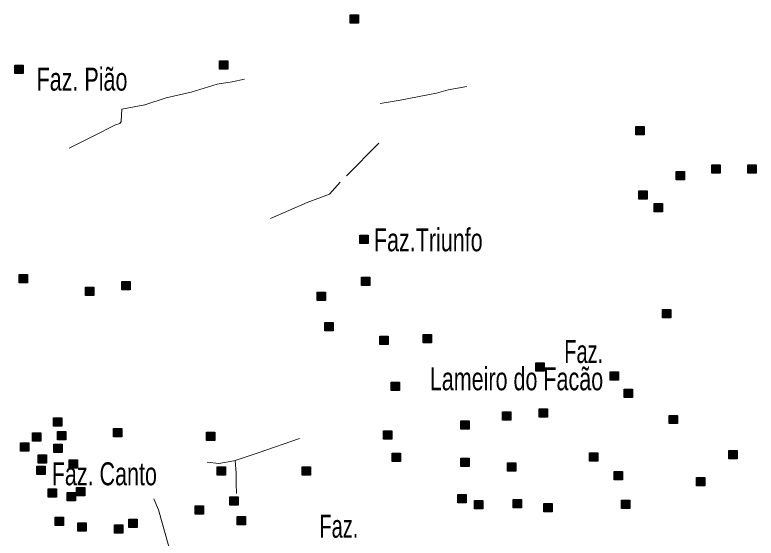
# Model space of a CAD drawing. Extents: x 445.4 to 500, y 8728.7 to 8784.
# Drawn here: x 494.63 to 499.79, y 8734.48 to 8738.12 of the extents above; entities that cross this region are included whole.
import ezdxf
from ezdxf.enums import TextEntityAlignment as Align

# ---------------------------------------------------------------- set-up
doc = ezdxf.new("R2010")
doc.units = 0
doc.header["$LTSCALE"] = 0.064
doc.linetypes.add('DOT_DASHED', pattern=[7.7, 5, -1.2, 0.3, -1.2])
doc.layers.add('2', color=7, linetype='Continuous', lineweight=25)
doc.layers.add('22', color=7, linetype='DOT_DASHED', lineweight=13)
doc.layers.add('61', color=7, linetype='Continuous')

msp = doc.modelspace()

# ---------------------------------------------------------------- hatches: boundary and pattern name
at = {"layer": '2'}
for points in [[(496.9631, 8738.124), (497.0211, 8738.124), (497.0211, 8738.066), (496.9631, 8738.066)], [(494.6266, 8737.7738), (494.6846, 8737.7738), (494.6846, 8737.7158), (494.6266, 8737.7158)], [(496.0512, 8737.8034), (496.1092, 8737.8034), (496.1092, 8737.7454), (496.0512, 8737.7454)], [(498.9517, 8737.3449), (499.0097, 8737.3449), (499.0097, 8737.2869), (498.9517, 8737.2869)], [(499.4806, 8737.0784), (499.5386, 8737.0784), (499.5386, 8737.0204), (499.4806, 8737.0204)], [(499.7323, 8737.0784), (499.7903, 8737.0784), (499.7903, 8737.0204), (499.7323, 8737.0204)], [(499.2326, 8737.031), (499.2906, 8737.031), (499.2906, 8736.973), (499.2326, 8736.973)], [(498.9735, 8736.897), (499.0315, 8736.897), (499.0315, 8736.839), (498.9735, 8736.839)], [(499.0794, 8736.8084), (499.1374, 8736.8084), (499.1374, 8736.7504), (499.0794, 8736.7504)], [(497.0302, 8736.5875), (497.0882, 8736.5875), (497.0882, 8736.5295), (497.0302, 8736.5295)], [(494.6562, 8736.314), (494.7142, 8736.314), (494.7142, 8736.256), (494.6562, 8736.256)], [(495.371, 8736.2647), (495.429, 8736.2647), (495.429, 8736.2067), (495.371, 8736.2067)], [(497.042, 8736.2943), (497.1, 8736.2943), (497.1, 8736.2363), (497.042, 8736.2363)], [(495.1196, 8736.2253), (495.1776, 8736.2253), (495.1776, 8736.1673), (495.1196, 8736.1673)], [(496.7314, 8736.1907), (496.7894, 8736.1907), (496.7894, 8736.1327), (496.7314, 8736.1327)], [(499.1377, 8736.0696), (499.1957, 8736.0696), (499.1957, 8736.0116), (499.1377, 8736.0116)], [(496.7857, 8735.9787), (496.8437, 8735.9787), (496.8437, 8735.9207), (496.7857, 8735.9207)], [(497.1701, 8735.885), (497.2281, 8735.885), (497.2281, 8735.827), (497.1701, 8735.827)], [(497.4708, 8735.8948), (497.5288, 8735.8948), (497.5288, 8735.8368), (497.4708, 8735.8368)], [(498.2546, 8735.6976), (498.3126, 8735.6976), (498.3126, 8735.6396), (498.2546, 8735.6396)], [(498.7729, 8735.6352), (498.8309, 8735.6352), (498.8309, 8735.5772), (498.7729, 8735.5772)], [(497.249, 8735.5644), (497.307, 8735.5644), (497.307, 8735.5064), (497.249, 8735.5064)], [(498.8714, 8735.5148), (498.9294, 8735.5148), (498.9294, 8735.4568), (498.8714, 8735.4568)], [(498.0229, 8735.3576), (498.0809, 8735.3576), (498.0809, 8735.2996), (498.0229, 8735.2996)], [(498.2792, 8735.377), (498.3372, 8735.377), (498.3372, 8735.319), (498.2792, 8735.319)], [(499.1851, 8735.3323), (499.2431, 8735.3323), (499.2431, 8735.2743), (499.1851, 8735.2743)], [(494.8955, 8735.3151), (494.9535, 8735.3151), (494.9535, 8735.2571), (494.8955, 8735.2571)], [(497.7321, 8735.2932), (497.7901, 8735.2932), (497.7901, 8735.2352), (497.7321, 8735.2352)], [(495.3133, 8735.2401), (495.3713, 8735.2401), (495.3713, 8735.1821), (495.3133, 8735.1821)], [(494.7499, 8735.2093), (494.8079, 8735.2093), (494.8079, 8735.1513), (494.7499, 8735.1513)], [(494.9239, 8735.2187), (494.9819, 8735.2187), (494.9819, 8735.1607), (494.9239, 8735.1607)], [(495.9625, 8735.2143), (496.0205, 8735.2143), (496.0205, 8735.1563), (495.9625, 8735.1563)], [(497.1948, 8735.2241), (497.2528, 8735.2241), (497.2528, 8735.1661), (497.1948, 8735.1661)], [(494.6661, 8735.1403), (494.7241, 8735.1403), (494.7241, 8735.0823), (494.6661, 8735.0823)], [(494.8977, 8735.1304), (494.9557, 8735.1304), (494.9557, 8735.0724), (494.8977, 8735.0724)], [(498.6292, 8735.0712), (498.6872, 8735.0712), (498.6872, 8735.0132), (498.6292, 8735.0132)], [(499.601, 8735.0878), (499.659, 8735.0878), (499.659, 8735.0298), (499.601, 8735.0298)], [(494.7893, 8735.0564), (494.8473, 8735.0564), (494.8473, 8734.9984), (494.7893, 8734.9984)], [(495.0062, 8735.0219), (495.0642, 8735.0219), (495.0642, 8734.9639), (495.0062, 8734.9639)], [(497.2554, 8735.068), (497.3134, 8735.068), (497.3134, 8735.01), (497.2554, 8735.01)], [(497.7342, 8735.0337), (497.7922, 8735.0337), (497.7922, 8734.9757), (497.7342, 8734.9757)], [(494.7794, 8734.9775), (494.8374, 8734.9775), (494.8374, 8734.9195), (494.7794, 8734.9195)], [(496.0364, 8734.9726), (496.0944, 8734.9726), (496.0944, 8734.9146), (496.0364, 8734.9146)], [(496.6279, 8734.9726), (496.6859, 8734.9726), (496.6859, 8734.9146), (496.6279, 8734.9146)], [(498.0574, 8735.0022), (498.1154, 8735.0022), (498.1154, 8734.9442), (498.0574, 8734.9442)], [(498.8021, 8734.9418), (498.8601, 8734.9418), (498.8601, 8734.8838), (498.8021, 8734.8838)], [(499.3748, 8734.898), (499.4328, 8734.898), (499.4328, 8734.84), (499.3748, 8734.84)], [(494.8583, 8734.8197), (494.9163, 8734.8197), (494.9163, 8734.7617), (494.8583, 8734.7617)], [(495.056, 8734.8294), (495.114, 8734.8294), (495.114, 8734.7714), (495.056, 8734.7714)], [(494.9914, 8734.7951), (495.0494, 8734.7951), (495.0494, 8734.7371), (494.9914, 8734.7371)], [(496.1251, 8734.7634), (496.1831, 8734.7634), (496.1831, 8734.7054), (496.1251, 8734.7054)], [(497.7131, 8734.7798), (497.7711, 8734.7798), (497.7711, 8734.7218), (497.7131, 8734.7218)], [(497.8291, 8734.7393), (497.8871, 8734.7393), (497.8871, 8734.6813), (497.8291, 8734.6813)], [(498.0968, 8734.7457), (498.1548, 8734.7457), (498.1548, 8734.6877), (498.0968, 8734.6877)], [(498.3116, 8734.7173), (498.3696, 8734.7173), (498.3696, 8734.6593), (498.3116, 8734.6593)], [(498.8532, 8734.741), (498.9112, 8734.741), (498.9112, 8734.683), (498.8532, 8734.683)], [(495.8837, 8734.7009), (495.9417, 8734.7009), (495.9417, 8734.6429), (495.8837, 8734.6429)], [(494.9076, 8734.6225), (494.9656, 8734.6225), (494.9656, 8734.5645), (494.9076, 8734.5645)], [(495.4202, 8734.6077), (495.4782, 8734.6077), (495.4782, 8734.5497), (495.4202, 8734.5497)], [(496.1744, 8734.6274), (496.2324, 8734.6274), (496.2324, 8734.5694), (496.1744, 8734.5694)], [(495.0653, 8734.583), (495.1233, 8734.583), (495.1233, 8734.525), (495.0653, 8734.525)], [(495.3217, 8734.5682), (495.3797, 8734.5682), (495.3797, 8734.5102), (495.3217, 8734.5102)]]:
    msp.add_hatch(color=256, dxfattribs=at).paths.add_polyline_path(points)

# ---------------------------------------------------------------- linework, layer by layer
for points in [[(496.9631, 8738.124), (497.0211, 8738.124), (497.0211, 8738.066), (496.9631, 8738.066)], [(494.6266, 8737.7738), (494.6846, 8737.7738), (494.6846, 8737.7158), (494.6266, 8737.7158)], [(496.0512, 8737.8034), (496.1092, 8737.8034), (496.1092, 8737.7454), (496.0512, 8737.7454)], [(498.9517, 8737.3449), (499.0097, 8737.3449), (499.0097, 8737.2869), (498.9517, 8737.2869)], [(499.4806, 8737.0784), (499.5386, 8737.0784), (499.5386, 8737.0204), (499.4806, 8737.0204)], [(499.7323, 8737.0784), (499.7903, 8737.0784), (499.7903, 8737.0204), (499.7323, 8737.0204)], [(499.2326, 8737.031), (499.2906, 8737.031), (499.2906, 8736.973), (499.2326, 8736.973)], [(498.9735, 8736.897), (499.0315, 8736.897), (499.0315, 8736.839), (498.9735, 8736.839)], [(499.0794, 8736.8084), (499.1374, 8736.8084), (499.1374, 8736.7504), (499.0794, 8736.7504)], [(497.0302, 8736.5875), (497.0882, 8736.5875), (497.0882, 8736.5295), (497.0302, 8736.5295)], [(494.6562, 8736.314), (494.7142, 8736.314), (494.7142, 8736.256), (494.6562, 8736.256)], [(495.371, 8736.2647), (495.429, 8736.2647), (495.429, 8736.2067), (495.371, 8736.2067)], [(497.042, 8736.2943), (497.1, 8736.2943), (497.1, 8736.2363), (497.042, 8736.2363)], [(495.1196, 8736.2253), (495.1776, 8736.2253), (495.1776, 8736.1673), (495.1196, 8736.1673)], [(496.7314, 8736.1907), (496.7894, 8736.1907), (496.7894, 8736.1327), (496.7314, 8736.1327)], [(499.1377, 8736.0696), (499.1957, 8736.0696), (499.1957, 8736.0116), (499.1377, 8736.0116)], [(496.7857, 8735.9787), (496.8437, 8735.9787), (496.8437, 8735.9207), (496.7857, 8735.9207)], [(497.1701, 8735.885), (497.2281, 8735.885), (497.2281, 8735.827), (497.1701, 8735.827)], [(497.4708, 8735.8948), (497.5288, 8735.8948), (497.5288, 8735.8368), (497.4708, 8735.8368)], [(498.2546, 8735.6976), (498.3126, 8735.6976), (498.3126, 8735.6396), (498.2546, 8735.6396)], [(498.7729, 8735.6352), (498.8309, 8735.6352), (498.8309, 8735.5772), (498.7729, 8735.5772)], [(497.249, 8735.5644), (497.307, 8735.5644), (497.307, 8735.5064), (497.249, 8735.5064)], [(498.8714, 8735.5148), (498.9294, 8735.5148), (498.9294, 8735.4568), (498.8714, 8735.4568)], [(498.0229, 8735.3576), (498.0809, 8735.3576), (498.0809, 8735.2996), (498.0229, 8735.2996)], [(498.2792, 8735.377), (498.3372, 8735.377), (498.3372, 8735.319), (498.2792, 8735.319)], [(499.1851, 8735.3323), (499.2431, 8735.3323), (499.2431, 8735.2743), (499.1851, 8735.2743)], [(494.8955, 8735.3151), (494.9535, 8735.3151), (494.9535, 8735.2571), (494.8955, 8735.2571)], [(497.7321, 8735.2932), (497.7901, 8735.2932), (497.7901, 8735.2352), (497.7321, 8735.2352)], [(495.3133, 8735.2401), (495.3713, 8735.2401), (495.3713, 8735.1821), (495.3133, 8735.1821)], [(494.7499, 8735.2093), (494.8079, 8735.2093), (494.8079, 8735.1513), (494.7499, 8735.1513)], [(494.9239, 8735.2187), (494.9819, 8735.2187), (494.9819, 8735.1607), (494.9239, 8735.1607)], [(495.9625, 8735.2143), (496.0205, 8735.2143), (496.0205, 8735.1563), (495.9625, 8735.1563)], [(497.1948, 8735.2241), (497.2528, 8735.2241), (497.2528, 8735.1661), (497.1948, 8735.1661)], [(494.6661, 8735.1403), (494.7241, 8735.1403), (494.7241, 8735.0823), (494.6661, 8735.0823)], [(494.8977, 8735.1304), (494.9557, 8735.1304), (494.9557, 8735.0724), (494.8977, 8735.0724)], [(498.6292, 8735.0712), (498.6872, 8735.0712), (498.6872, 8735.0132), (498.6292, 8735.0132)], [(499.601, 8735.0878), (499.659, 8735.0878), (499.659, 8735.0298), (499.601, 8735.0298)], [(494.7893, 8735.0564), (494.8473, 8735.0564), (494.8473, 8734.9984), (494.7893, 8734.9984)], [(495.0062, 8735.0219), (495.0642, 8735.0219), (495.0642, 8734.9639), (495.0062, 8734.9639)], [(497.2554, 8735.068), (497.3134, 8735.068), (497.3134, 8735.01), (497.2554, 8735.01)], [(497.7342, 8735.0337), (497.7922, 8735.0337), (497.7922, 8734.9757), (497.7342, 8734.9757)], [(494.7794, 8734.9775), (494.8374, 8734.9775), (494.8374, 8734.9195), (494.7794, 8734.9195)], [(496.0364, 8734.9726), (496.0944, 8734.9726), (496.0944, 8734.9146), (496.0364, 8734.9146)], [(496.6279, 8734.9726), (496.6859, 8734.9726), (496.6859, 8734.9146), (496.6279, 8734.9146)], [(498.0574, 8735.0022), (498.1154, 8735.0022), (498.1154, 8734.9442), (498.0574, 8734.9442)], [(498.8021, 8734.9418), (498.8601, 8734.9418), (498.8601, 8734.8838), (498.8021, 8734.8838)], [(499.3748, 8734.898), (499.4328, 8734.898), (499.4328, 8734.84), (499.3748, 8734.84)], [(494.8583, 8734.8197), (494.9163, 8734.8197), (494.9163, 8734.7617), (494.8583, 8734.7617)], [(495.056, 8734.8294), (495.114, 8734.8294), (495.114, 8734.7714), (495.056, 8734.7714)], [(494.9914, 8734.7951), (495.0494, 8734.7951), (495.0494, 8734.7371), (494.9914, 8734.7371)], [(496.1251, 8734.7634), (496.1831, 8734.7634), (496.1831, 8734.7054), (496.1251, 8734.7054)], [(497.7131, 8734.7798), (497.7711, 8734.7798), (497.7711, 8734.7218), (497.7131, 8734.7218)], [(497.8291, 8734.7393), (497.8871, 8734.7393), (497.8871, 8734.6813), (497.8291, 8734.6813)], [(498.0968, 8734.7457), (498.1548, 8734.7457), (498.1548, 8734.6877), (498.0968, 8734.6877)], [(498.3116, 8734.7173), (498.3696, 8734.7173), (498.3696, 8734.6593), (498.3116, 8734.6593)], [(498.8532, 8734.741), (498.9112, 8734.741), (498.9112, 8734.683), (498.8532, 8734.683)], [(495.8837, 8734.7009), (495.9417, 8734.7009), (495.9417, 8734.6429), (495.8837, 8734.6429)], [(494.9076, 8734.6225), (494.9656, 8734.6225), (494.9656, 8734.5645), (494.9076, 8734.5645)], [(495.4202, 8734.6077), (495.4782, 8734.6077), (495.4782, 8734.5497), (495.4202, 8734.5497)], [(496.1744, 8734.6274), (496.2324, 8734.6274), (496.2324, 8734.5694), (496.1744, 8734.5694)], [(495.0653, 8734.583), (495.1233, 8734.583), (495.1233, 8734.525), (495.0653, 8734.525)], [(495.3217, 8734.5682), (495.3797, 8734.5682), (495.3797, 8734.5102), (495.3217, 8734.5102)]]:
    msp.add_lwpolyline(points, close=True, dxfattribs=at)
at = {"layer": '22'}
for points in [[(495.0042, 8737.1947), (495.1727, 8737.279), (495.3277, 8737.3577), (495.3572, 8737.3675), (495.3671, 8737.3798), (495.372, 8737.4658), (495.532, 8737.4977), (495.6796, 8737.5444), (495.8543, 8737.5838), (496.0364, 8737.6403), (496.1398, 8737.6575), (496.2262, 8737.6752)], [(497.172, 8737.5055), (497.3102, 8737.5282), (497.5634, 8737.579), (497.6446, 8737.6013), (497.7753, 8737.6245)], [(497.1614, 8737.2291), (496.8931, 8736.9583), (496.8183, 8736.8733), (496.6618, 8736.8156), (496.4067, 8736.7035)], [(496.6101, 8735.1708), (496.3286, 8735.0741), (496.1614, 8735.0175)], [(496.1614, 8735.0175), (496.1517, 8735.0152), (496.0484, 8734.9967), (495.9671, 8735.0054)], [(496.1614, 8735.0175), (496.1685, 8734.9287), (496.1685, 8734.8575), (496.1711, 8734.7886)], [(495.594, 8734.7512), (495.6264, 8734.6731), (495.6949, 8734.4352), (495.8021, 8734.0663), (495.8436, 8733.7581), (495.8853, 8733.3327)]]:
    msp.add_lwpolyline(points, dxfattribs=at)

# ---------------------------------------------------------------- texts
at = {"layer": '61', "width": 0.7}
for s, p in [('Faz. Pião', (494.7783, 8737.5955)), ('Faz.Triunfo', (497.1276, 8736.4758)), ('Faz. Canto', (494.8838, 8734.8448))]:
    msp.add_text(s, height=0.16, dxfattribs=at).set_placement(p)
at = {"layer": '61'}
for s, width, p in [('Faz.', 0.65, (498.7245, 8735.6969)), ('Lameiro do Facão', 0.7, (498.7245, 8735.5069)), ('Faz.', 0.65, (497.0187, 8734.4793))]:
    msp.add_text(s, height=0.16, dxfattribs=dict(at, width=width)).set_placement(p, align=Align.RIGHT)

doc.saveas('drawing.dxf')
